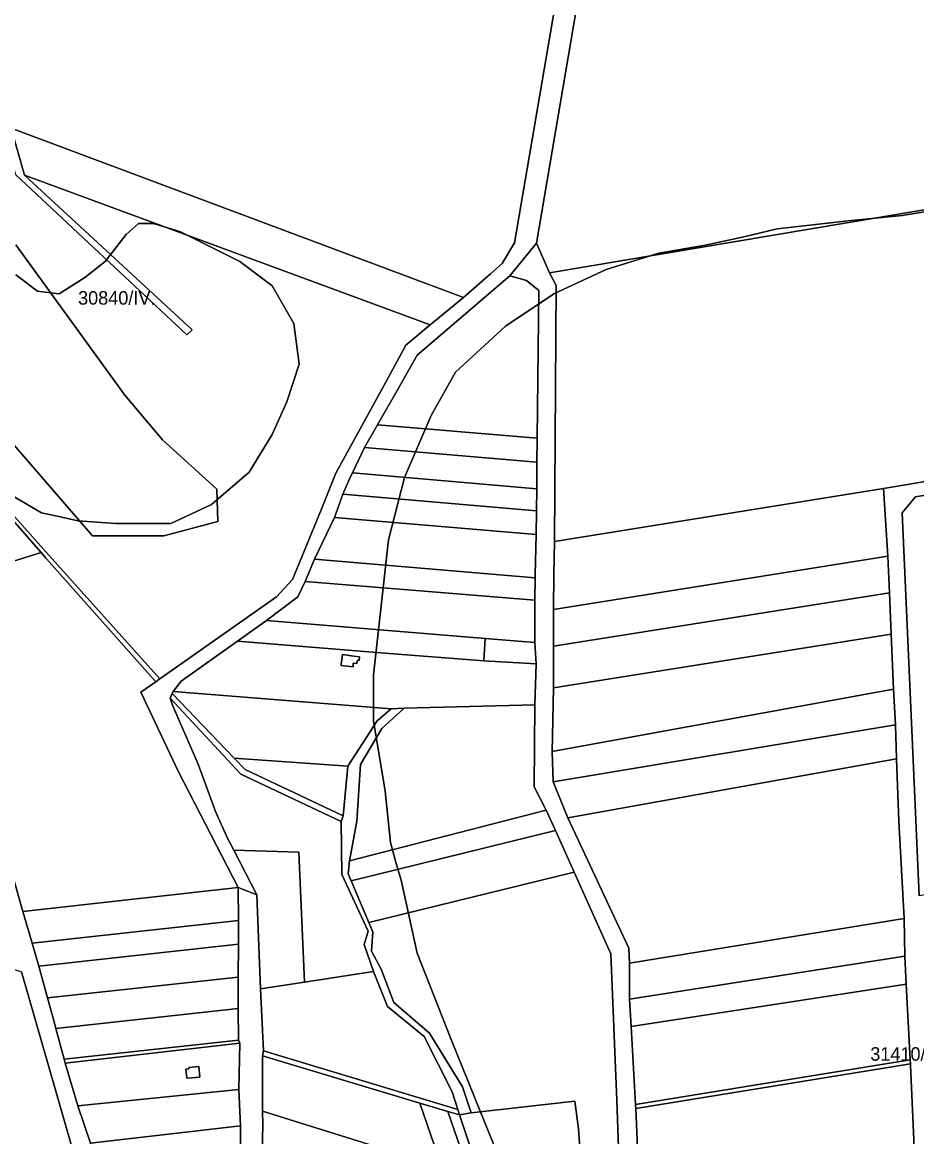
# Model space of a CAD drawing. Extents: x -541351 to -537540, y -1162694 to -1159725.
# Drawn here: x -540116.8 to -539785.9, y -1160827.9 to -1160415.5 of the extents above; entities that cross this region are included whole.
import ezdxf

# ---------------------------------------------------------------- set-up
doc = ezdxf.new("R2010")
doc.units = 0
for name, color, linetype in [('95560013', 7, 'Continuous'), ('95590013', 7, 'Continuous'), ('95600013', 7, 'Continuous'), ('95610013', 7, 'Continuous'), ('95620013', 7, 'Continuous'), ('95630013', 7, 'Continuous'), ('95640013', 7, 'Continuous'), ('95660013', 7, 'Continuous')]:
    doc.layers.add(name, color=color, linetype=linetype)

msp = doc.modelspace()

# ---------------------------------------------------------------- linework, layer by layer
at = {"layer": '95560013'}
for points in [[(-539919.82, -1160409.86), (-539934.65, -1160497.18), (-539939.3, -1160504.82), (-539943.59, -1160508.57), (-539953.62, -1160517.32), (-540120.93, -1160454.7), (-540124.57, -1160440.83), (-540129.29, -1160422.87), (-540136.74, -1160394.52), (-540133.58, -1160382.33), (-540128.1, -1160326.8), (-540126.4, -1160311.55), (-540100.25, -1160312.92), (-540099.35, -1160311.53), (-540097.45, -1160311.62), (-540018.39, -1160316.26), (-539910.82, -1160357.17), (-539913.57, -1160373.29), (-539923.43, -1160371.6), (-539925.11, -1160381.46), (-539915.26, -1160383.15)], [(-539622.59, -1160379.21), (-539631.8, -1160405.4), (-539638.38, -1160424.12), (-539641.15, -1160432), (-539644.34, -1160446.97), (-539647.54, -1160461.93), (-539784.61, -1160485.12), (-539921.72, -1160508.25), (-539926.62, -1160497.29), (-539911.84, -1160410.99), (-539905.99, -1160405.21), (-539806.59, -1160389.16), (-539702.88, -1160371.48), (-539612.64, -1160356.38), (-539617.44, -1160367.38)], [(-540115.93, -1160472.05), (-540120.93, -1160454.7), (-539953.62, -1160517.32), (-539965.88, -1160527.52)], [(-539650.35, -1160547.02), (-539662.68, -1160547.97), (-539661.99, -1160565.14), (-539713.66, -1160573.83), (-539798.17, -1160588.09), (-539919.97, -1160607.67), (-539919.25, -1160512.88), (-539921.72, -1160508.25), (-539784.61, -1160485.12), (-539647.54, -1160461.93), (-539647.95, -1160463.89), (-539649.83, -1160472.69), (-539650.25, -1160485.84), (-539650.77, -1160502.39), (-539651.71, -1160531.92)], [(-539646.24, -1160640.35), (-539641.09, -1160669.51), (-539631.78, -1160712.13), (-539785.07, -1160738.8), (-539786.27, -1160710.83), (-539791.3, -1160596.99), (-539786.42, -1160591.13), (-539713.08, -1160578.81), (-539650.68, -1160568.9), (-539649.42, -1160590.92), (-539649.14, -1160598.17)], [(-539919.97, -1160607.67), (-539798.17, -1160588.09), (-539796.58, -1160613.04), (-539920.26, -1160632.77), (-539920.13, -1160619.57)], [(-539920.26, -1160632.77), (-539796.58, -1160613.04), (-539796, -1160626.63), (-539920.3, -1160646.37)], [(-539795.42, -1160641.97), (-539920.31, -1160661.82), (-539920.3, -1160646.37), (-539796, -1160626.63)], [(-539920.81, -1160685.37), (-539920.31, -1160661.82), (-539795.42, -1160641.97), (-539794.54, -1160662.36)], [(-539927.15, -1160668.08), (-539927.4, -1160698.47), (-539922.93, -1160707.08), (-539995.79, -1160725.79), (-539993.04, -1160711.11), (-539991.63, -1160690.18), (-539983.78, -1160676.86), (-539975.53, -1160669.32)], [(-539793.44, -1160688.13), (-539792.5, -1160711.11), (-539790.59, -1160747.18), (-539892.18, -1160763.74), (-539892.42, -1160758.15), (-539914.96, -1160709.96)], [(-539995.79, -1160725.79), (-539922.93, -1160707.08), (-539919.56, -1160714.56), (-539995.18, -1160733.22), (-539996.27, -1160730.67)], [(-539790.3, -1160761.11), (-539892.16, -1160776.96), (-539892.18, -1160763.74), (-539790.59, -1160747.18)], [(-539891.58, -1160787.19), (-539892.16, -1160776.96), (-539790.3, -1160761.11), (-539789.83, -1160771.45)], [(-539889.9, -1160816.04), (-539891.58, -1160787.19), (-539789.83, -1160771.45), (-539788.31, -1160799.43)], [(-539889.83, -1160817.49), (-539889.9, -1160816.04), (-539788.31, -1160799.43), (-539788.24, -1160800.92)]]:
    msp.add_lwpolyline(points, close=True, dxfattribs=at)
msp.add_lwpolyline([(-540119.13, -1160497.83), (-540078.88, -1160553.44), (-540064.98, -1160570.08), (-540044.86, -1160588.28), (-540044.48, -1160600.22), (-540064.4, -1160605.52), (-540090.77, -1160605.52), (-540122.99, -1160568.3)], dxfattribs=at)
at = {"layer": '95590013'}
for points in [[(-539995.23, -1160583.36), (-539994.66, -1160582.19), (-539926.44, -1160588.21), (-539926.57, -1160596.26), (-539998.21, -1160590.13)], [(-540001.27, -1160598.81), (-539998.21, -1160590.13), (-539926.57, -1160596.26), (-539926.64, -1160605.06)], [(-539927.02, -1160621.09), (-540008.66, -1160614.23), (-540001.27, -1160598.81), (-539926.64, -1160605.06), (-539927, -1160620.15)], [(-540012.11, -1160622.44), (-540008.66, -1160614.23), (-539927.02, -1160621.09), (-539927.13, -1160629.39)], [(-539945.53, -1160643.52), (-540026.44, -1160636.89), (-540014.85, -1160628.17), (-540012.11, -1160622.44), (-539927.13, -1160629.39), (-539927.14, -1160645.03)], [(-540037.21, -1160644.48), (-540026.44, -1160636.89), (-539945.53, -1160643.52), (-539946.11, -1160651.83), (-539981.02, -1160649.08)], [(-540057.96, -1160659.35), (-540037.21, -1160644.48), (-539981.02, -1160649.08), (-539946.11, -1160651.83), (-539926.65, -1160652.88), (-539927.15, -1160668.08), (-539975.53, -1160669.32), (-539980.29, -1160669.52), (-540060.96, -1160663.22)], [(-539992.79, -1160651.59), (-539992.18, -1160651.66), (-539992.03, -1160650.28), (-539994.09, -1160650.04), (-539998.3, -1160649.52), (-539998.78, -1160653.06), (-539998.83, -1160653.54), (-539994.44, -1160654.04), (-539994.37, -1160652.73), (-539993.07, -1160652.86)], [(-540061.35, -1160663.86), (-540060.96, -1160663.22), (-539980.29, -1160669.52), (-539985.54, -1160673.96), (-539996.34, -1160690.78), (-540038.38, -1160687.86)], [(-540034.4, -1160692.02), (-540038.38, -1160687.86), (-539996.34, -1160690.78), (-539998.13, -1160709.19)], [(-539995.18, -1160733.22), (-539919.56, -1160714.56), (-539912.63, -1160729.97), (-539988.6, -1160748.68)], [(-540012.41, -1160770.69), (-540028.72, -1160773.19), (-540030.03, -1160738.43), (-540038.55, -1160721.9), (-540014.46, -1160722.6)], [(-540036.86, -1160747.95), (-540113.13, -1160756.33), (-540116.53, -1160744.57), (-540036.88, -1160735.75)], [(-540036.86, -1160747.95), (-540036.79, -1160756.7), (-540110.71, -1160764.79), (-540113.13, -1160756.33)], [(-540107.47, -1160776.56), (-540110.71, -1160764.79), (-540036.79, -1160756.7), (-540036.94, -1160768.85)], [(-540036.99, -1160780.5), (-540104.44, -1160787.85), (-540105.34, -1160784.11), (-540107.47, -1160776.56), (-540036.94, -1160768.85)], [(-539986.83, -1160766.76), (-539981.63, -1160779.68), (-539968.08, -1160790.81), (-539957.74, -1160811.35), (-539955.72, -1160817.82), (-540027.5, -1160796.19), (-540028.72, -1160773.19), (-540012.41, -1160770.69)], [(-540104.44, -1160787.85), (-540036.99, -1160780.5), (-540036.76, -1160792.2), (-540101.24, -1160799.21)], [(-540096.19, -1160816.54), (-540100.88, -1160800.67), (-540036.32, -1160793.36), (-540036.7, -1160810.45)], [(-540027.87, -1160797.94), (-539969.72, -1160815.45), (-539961.62, -1160839.25), (-540027.93, -1160818.42)], [(-540055.19, -1160802.81), (-540056.23, -1160802.89), (-540055.96, -1160806.31), (-540051.08, -1160805.92), (-540051.48, -1160801.91), (-540055.23, -1160802.25)], [(-540036.01, -1160823.95), (-540091.53, -1160830.3), (-540096.19, -1160816.54), (-540036.7, -1160810.45)], [(-539944.35, -1160866.97), (-539965.12, -1160860.37), (-540028.13, -1160840.36), (-540027.8, -1160823.41), (-540027.93, -1160818.42), (-539961.62, -1160839.25), (-539951.15, -1160842.57), (-539945.91, -1160858.23)], [(-540091.53, -1160830.3), (-540036.01, -1160823.95), (-540036.02, -1160838.65), (-540087.52, -1160844.38)]]:
    msp.add_lwpolyline(points, close=True, dxfattribs=at)
at = {"layer": '95600013'}
for points in [[(-539920.81, -1160685.37), (-539794.54, -1160662.36), (-539793.73, -1160675.44), (-539920.42, -1160696.57)], [(-539920.42, -1160696.57), (-539793.73, -1160675.44), (-539793.44, -1160688.13), (-539914.96, -1160709.96)], [(-539786.77, -1160834.66), (-539888.46, -1160851.17), (-539888.8, -1160841.12), (-539889.83, -1160817.49), (-539788.24, -1160800.92), (-539788.22, -1160801.5)], [(-539950.7, -1160819.03), (-539912.4, -1160814.78), (-539911.06, -1160825.04), (-539910.09, -1160839.54), (-539907.82, -1160871.9), (-539906.01, -1160880.97), (-539904.22, -1160885.41), (-539914.91, -1160883.79), (-539933.13, -1160881.03), (-539940.65, -1160870.01), (-539941.62, -1160860.32), (-539955.05, -1160819.87)]]:
    msp.add_lwpolyline(points, close=True, dxfattribs=at)
msp.add_lwpolyline([(-539910.09, -1160839.54), (-539911.06, -1160825.04), (-539912.4, -1160814.78), (-539950.7, -1160819.03), (-539953.94, -1160809.51), (-539966.11, -1160789.54), (-539979.29, -1160778.28), (-539984.04, -1160765.87), (-539987.59, -1160759.2), (-539987.15, -1160752.09), (-539988.6, -1160748.68), (-539912.63, -1160729.97), (-539899.02, -1160760.22), (-539896.91, -1160814.58), (-539895.82, -1160842.53)], dxfattribs=at)
at = {"layer": '95610013'}
for points in [[(-540119.18, -1160471.96), (-540055.96, -1160531.12), (-540053.98, -1160529.34), (-540115.93, -1160472.05), (-539965.88, -1160527.52), (-539974.94, -1160535.05), (-539982.2, -1160548.43), (-540000.86, -1160582.31), (-540006.23, -1160595.9), (-540016.83, -1160621.72), (-540022.71, -1160628.19), (-540065.89, -1160658.49), (-540107.96, -1160611.59), (-540141.33, -1160574.15)], [(-540122.99, -1160568.3), (-540090.77, -1160605.52), (-540064.4, -1160605.52), (-540044.48, -1160600.22), (-540044.86, -1160588.28), (-540064.98, -1160570.08), (-540078.88, -1160553.44), (-540119.13, -1160497.83)]]:
    msp.add_lwpolyline(points, dxfattribs=at)
for points in [[(-539985.34, -1160564.48), (-539977.15, -1160550.1), (-539970.76, -1160538.64), (-539936.38, -1160509.39), (-539930.23, -1160511.03), (-539925.73, -1160514.82), (-539926.28, -1160569.47)], [(-539990.15, -1160572.92), (-539985.34, -1160564.48), (-539926.28, -1160569.47), (-539926.48, -1160578.26)], [(-540161.5, -1160586.91), (-540163.58, -1160579.77), (-540146.72, -1160569.77), (-540109.81, -1160611.78), (-540140.65, -1160621.39), (-540150.87, -1160624.16)], [(-539926.48, -1160578.26), (-539926.44, -1160588.21), (-539994.66, -1160582.19), (-539990.15, -1160572.92)], [(-540116.53, -1160744.57), (-540133.22, -1160686.01), (-540150.39, -1160625.84), (-540150.87, -1160624.16), (-540140.65, -1160621.39), (-540109.81, -1160611.78), (-540108.07, -1160613.76), (-540107.83, -1160614.04), (-540067.41, -1160659.58), (-540072.96, -1160663.43), (-540059.03, -1160692.85), (-540036.88, -1160735.75)]]:
    msp.add_lwpolyline(points, close=True, dxfattribs=at)
at = {"layer": '95620013'}
msp.add_lwpolyline([(-540012.41, -1160770.69), (-540014.46, -1160722.6), (-540038.55, -1160721.9), (-540040.97, -1160717.22), (-540045.29, -1160707.57), (-540051.73, -1160690.03), (-540061.25, -1160668.23), (-540062.12, -1160665.66), (-540036, -1160693.7), (-539998.88, -1160711.28), (-539998.62, -1160730.92), (-539988.79, -1160751.87), (-539990.3, -1160756.79), (-539986.83, -1160766.76)], close=True, dxfattribs=at)
at = {"layer": '95630013'}
msp.add_lwpolyline([(-539988.6, -1160748.68), (-539987.15, -1160752.09), (-539987.59, -1160759.2), (-539984.04, -1160765.87), (-539979.29, -1160778.28), (-539966.11, -1160789.54), (-539953.94, -1160809.51), (-539950.7, -1160819.03), (-539955.05, -1160819.87), (-539955.72, -1160817.82), (-539957.74, -1160811.35), (-539968.08, -1160790.81), (-539981.63, -1160779.68), (-539986.83, -1160766.76), (-539990.3, -1160756.79), (-539988.79, -1160751.87), (-539998.62, -1160730.92), (-539998.88, -1160711.28), (-539998.13, -1160709.19), (-539996.34, -1160690.78), (-539985.54, -1160673.96), (-539980.29, -1160669.52), (-539975.53, -1160669.32), (-539983.78, -1160676.86), (-539991.63, -1160690.18), (-539993.04, -1160711.11), (-539995.79, -1160725.79), (-539996.27, -1160730.67), (-539995.18, -1160733.22)], close=True, dxfattribs=at)
msp.add_lwpolyline([(-539951.15, -1160842.57), (-539959.33, -1160818.58), (-539955.05, -1160819.87), (-539941.62, -1160860.32)], dxfattribs=at)
at = {"layer": '95640013'}
for points in [[(-539911.84, -1160410.99), (-539926.62, -1160497.29), (-539936.38, -1160509.39), (-539970.76, -1160538.64), (-539977.15, -1160550.1), (-539985.34, -1160564.48), (-539990.15, -1160572.92), (-539994.66, -1160582.19), (-539995.23, -1160583.36), (-539998.21, -1160590.13), (-540001.27, -1160598.81), (-540008.66, -1160614.23), (-540012.11, -1160622.44), (-540014.85, -1160628.17), (-540026.44, -1160636.89), (-540037.21, -1160644.48), (-540057.96, -1160659.35), (-540060.96, -1160663.22), (-540061.35, -1160663.86), (-540062.12, -1160665.66), (-540061.25, -1160668.23), (-540051.73, -1160690.03), (-540045.29, -1160707.57), (-540040.97, -1160717.22), (-540038.55, -1160721.9), (-540030.03, -1160738.43), (-540036.88, -1160735.75), (-540059.03, -1160692.85), (-540072.96, -1160663.43), (-540067.41, -1160659.58), (-540065.89, -1160658.49), (-540022.71, -1160628.19), (-540016.83, -1160621.72), (-540006.23, -1160595.9), (-540000.86, -1160582.31), (-539982.2, -1160548.43), (-539974.94, -1160535.05), (-539965.88, -1160527.52), (-539953.62, -1160517.32), (-539943.59, -1160508.57), (-539939.3, -1160504.82), (-539934.65, -1160497.18), (-539919.82, -1160409.86)], [(-539895.82, -1160842.53), (-539896.91, -1160814.58), (-539899.02, -1160760.22), (-539912.63, -1160729.97), (-539919.56, -1160714.56), (-539922.93, -1160707.08), (-539927.4, -1160698.47), (-539927.15, -1160668.08), (-539926.65, -1160652.88), (-539927.14, -1160645.03), (-539927.13, -1160629.39), (-539927.02, -1160621.09), (-539927, -1160620.15), (-539926.64, -1160605.06), (-539926.57, -1160596.26), (-539926.44, -1160588.21), (-539926.48, -1160578.26), (-539926.28, -1160569.47), (-539925.73, -1160514.82), (-539930.23, -1160511.03), (-539936.38, -1160509.39), (-539926.62, -1160497.29), (-539921.72, -1160508.25), (-539919.25, -1160512.88), (-539919.97, -1160607.67), (-539920.13, -1160619.57), (-539920.26, -1160632.77), (-539920.3, -1160646.37), (-539920.31, -1160661.82), (-539920.81, -1160685.37), (-539920.42, -1160696.57), (-539914.96, -1160709.96), (-539892.42, -1160758.15), (-539892.18, -1160763.74), (-539892.16, -1160776.96), (-539891.58, -1160787.19), (-539889.9, -1160816.04), (-539889.83, -1160817.49), (-539888.8, -1160841.12)], [(-539786.77, -1160834.66), (-539788.22, -1160801.5), (-539788.24, -1160800.92), (-539788.31, -1160799.43), (-539789.83, -1160771.45), (-539790.3, -1160761.11), (-539790.59, -1160747.18), (-539792.5, -1160711.11), (-539793.44, -1160688.13), (-539793.73, -1160675.44), (-539794.54, -1160662.36), (-539795.42, -1160641.97), (-539796, -1160626.63), (-539796.58, -1160613.04), (-539798.17, -1160588.09), (-539713.66, -1160573.83)], [(-539713.08, -1160578.81), (-539786.42, -1160591.13), (-539791.3, -1160596.99), (-539786.27, -1160710.83), (-539785.07, -1160738.8)], [(-540133.22, -1160686.01), (-540116.53, -1160744.57), (-540113.13, -1160756.33), (-540110.71, -1160764.79), (-540107.47, -1160776.56), (-540105.34, -1160784.11), (-540104.44, -1160787.85), (-540101.24, -1160799.21), (-540100.88, -1160800.67), (-540096.19, -1160816.54), (-540091.53, -1160830.3)], [(-540036.02, -1160838.65), (-540036.01, -1160823.95), (-540036.7, -1160810.45), (-540036.32, -1160793.36), (-540036.76, -1160792.2), (-540036.99, -1160780.5), (-540036.94, -1160768.85), (-540036.79, -1160756.7), (-540036.86, -1160747.95), (-540036.88, -1160735.75), (-540030.03, -1160738.43), (-540028.72, -1160773.19), (-540027.5, -1160796.19), (-540027.87, -1160797.94), (-540027.93, -1160818.42), (-540027.8, -1160823.41), (-540028.13, -1160840.36)], [(-540183.69, -1160843.89), (-540189.73, -1160823.53), (-540168.1, -1160773.35), (-540159.87, -1160754.25), (-540159.21, -1160752.73), (-540157.05, -1160753.39), (-540148.41, -1160756.31), (-540137.65, -1160759.94), (-540129.12, -1160762.82), (-540117.04, -1160766.9), (-540090.94, -1160857.78)], [(-540090.94, -1160857.78), (-540117.04, -1160766.9)]]:
    msp.add_lwpolyline(points, dxfattribs=at)
for points in [[(-540053.98, -1160529.34), (-540055.96, -1160531.12), (-540119.18, -1160471.96), (-540123.88, -1160455.21), (-540132.3, -1160421.84), (-540129.29, -1160422.87), (-540124.57, -1160440.83), (-540120.93, -1160454.7), (-540115.93, -1160472.05)], [(-540109.81, -1160611.78), (-540146.72, -1160569.77), (-540145.68, -1160569.15), (-540141.33, -1160574.15), (-540107.96, -1160611.59), (-540065.89, -1160658.49), (-540067.41, -1160659.58), (-540107.83, -1160614.04), (-540108.07, -1160613.76)], [(-539945.53, -1160643.52), (-539927.14, -1160645.03), (-539926.65, -1160652.88), (-539946.11, -1160651.83)], [(-539992.79, -1160651.59), (-539993.07, -1160652.86), (-539994.37, -1160652.73), (-539994.44, -1160654.04), (-539998.83, -1160653.54), (-539998.78, -1160653.06), (-539998.3, -1160649.52), (-539994.09, -1160650.04), (-539992.03, -1160650.28), (-539992.18, -1160651.66)], [(-540036, -1160693.7), (-540062.12, -1160665.66), (-540061.35, -1160663.86), (-540038.38, -1160687.86), (-540034.4, -1160692.02), (-539998.13, -1160709.19), (-539998.88, -1160711.28)], [(-540100.88, -1160800.67), (-540101.24, -1160799.21), (-540036.76, -1160792.2), (-540036.32, -1160793.36)], [(-539959.33, -1160818.58), (-539969.72, -1160815.45), (-540027.87, -1160797.94), (-540027.5, -1160796.19), (-539955.72, -1160817.82), (-539955.05, -1160819.87)], [(-540051.48, -1160801.91), (-540051.08, -1160805.92), (-540055.96, -1160806.31), (-540056.23, -1160802.89), (-540055.19, -1160802.81), (-540055.23, -1160802.25)], [(-539969.72, -1160815.45), (-539959.33, -1160818.58), (-539951.15, -1160842.57), (-539961.62, -1160839.25)]]:
    msp.add_lwpolyline(points, close=True, dxfattribs=at)
at = {"layer": '95660013'}
for points in [[(-539748.31, -1160480), (-539791.31, -1160487), (-539811.31, -1160489), (-539837.5, -1160492), (-539850.37, -1160495), (-539864.19, -1160498), (-539881.37, -1160501), (-539900.81, -1160507), (-539920.12, -1160516), (-539938, -1160528), (-539956.5, -1160545), (-539965.5, -1160561), (-539975.37, -1160584), (-539981.37, -1160607), (-539986.81, -1160657), (-539986.81, -1160674), (-539982.5, -1160700), (-539980.62, -1160719), (-539978.44, -1160726.78), (-539976.69, -1160733), (-539970.69, -1160760), (-539958.19, -1160792), (-539949.49, -1160813.33), (-539938.62, -1160840)], [(-539938.62, -1160840), (-539949.49, -1160813.33), (-539958.19, -1160792), (-539970.69, -1160760), (-539976.69, -1160733), (-539978.44, -1160726.78), (-539980.62, -1160719), (-539982.5, -1160700), (-539986.81, -1160674), (-539986.81, -1160657), (-539981.37, -1160607), (-539975.37, -1160584), (-539965.5, -1160561), (-539956.5, -1160545), (-539938, -1160528), (-539920.12, -1160516), (-539900.81, -1160507), (-539881.37, -1160501), (-539864.19, -1160498), (-539850.37, -1160495), (-539837.5, -1160492), (-539811.31, -1160489), (-539791.31, -1160487), (-539748.31, -1160480)], [(-540119.12, -1160509), (-540111.12, -1160515), (-540103.12, -1160516), (-540093.69, -1160510), (-540086.19, -1160504), (-540078.31, -1160494), (-540073.81, -1160490), (-540068.31, -1160490), (-540058.31, -1160493), (-540036.37, -1160504), (-540024.37, -1160513), (-540016.37, -1160527), (-540014.37, -1160542), (-540018.87, -1160556), (-540024.37, -1160568), (-540032.87, -1160582), (-540046.81, -1160594), (-540061.81, -1160601), (-540082.19, -1160601), (-540096.19, -1160600), (-540102.16, -1160598.67), (-540109.62, -1160597), (-540135.5, -1160582)], [(-540135.5, -1160582), (-540109.62, -1160597), (-540102.16, -1160598.67), (-540096.19, -1160600), (-540082.19, -1160601), (-540061.81, -1160601), (-540046.81, -1160594), (-540032.87, -1160582), (-540024.37, -1160568), (-540018.87, -1160556), (-540014.37, -1160542), (-540016.37, -1160527), (-540024.37, -1160513), (-540036.37, -1160504), (-540058.31, -1160493), (-540068.31, -1160490), (-540073.81, -1160490), (-540078.31, -1160494), (-540086.19, -1160504), (-540093.69, -1160510), (-540103.12, -1160516), (-540111.12, -1160515), (-540119.12, -1160509)]]:
    msp.add_lwpolyline(points, dxfattribs=at)

# ---------------------------------------------------------------- texts
for s, p in [('30840/IV.', (-540096.15, -1160520)), ('31410/III.', (-539803.09, -1160799.79))]:
    msp.add_text(s, height=5, rotation=0, dxfattribs=at).set_placement(p)

doc.saveas('drawing.dxf')
